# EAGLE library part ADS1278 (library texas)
Quad/Octal, Simultaneous Sampling, 24-Bit Analog-to-Digital Converters ADS1274 / ADS1278 Auto generated by make-symbol-device-package-bsdl.ulp Rev. 29 Source: http://focus.ti.com/lit/ds/symlink/ads1274.pdf
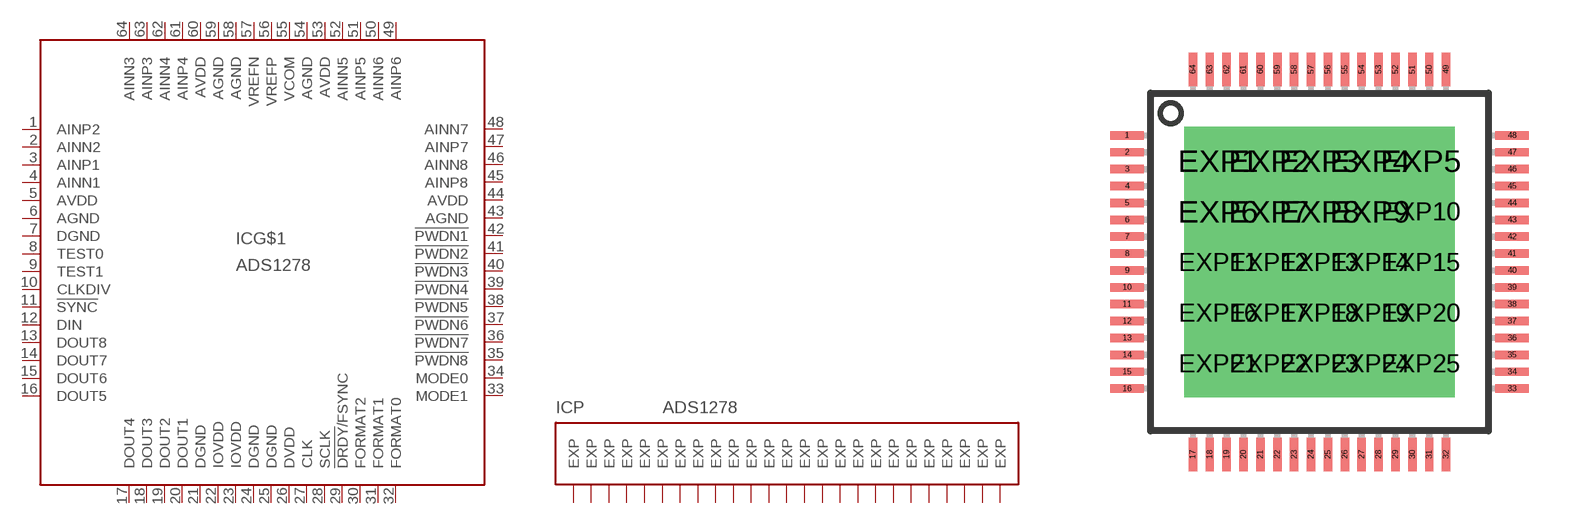
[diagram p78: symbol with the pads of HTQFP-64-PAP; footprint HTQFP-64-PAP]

Designator prefix IC; gates G$1=ADS1278 P=EXP25

## ADS1278 (MPN: ADS1278IPAPT; OC_FARNELL: 1603419; OC_NEWARK: 50M8811)  [HTQFP-64-PAP]
1  G$1:AINP2  in
2  G$1:AINN2  in
3  G$1:AINP1  in
4  G$1:AINN1  in
5  G$1:AVDD  pwr
6  G$1:AGND  pwr
7  G$1:DGND  pwr
8  G$1:TEST0  in
9  G$1:TEST1  in
10  G$1:CLKDIV  in
11  G$1:!SYNC  in
12  G$1:DIN  in
13  G$1:DOUT8  out
14  G$1:DOUT7  out
15  G$1:DOUT6  out
16  G$1:DOUT5  out
17  G$1:DOUT4  out
18  G$1:DOUT3  out
19  G$1:DOUT2  out
20  G$1:DOUT1  out
21  G$1:DGND  pwr
22  G$1:IOVDD  pwr
23  G$1:IOVDD  pwr
24  G$1:DGND  pwr
25  G$1:DGND  pwr
26  G$1:DVDD  pwr
27  G$1:CLK  in
28  G$1:SCLK
29  G$1:!DRDY!/FSYNC
30  G$1:FORMAT2  in
31  G$1:FORMAT1  in
32  G$1:FORMAT0  in
33  G$1:MODE1  in
34  G$1:MODE0  in
35  G$1:!PWDN8  in
36  G$1:!PWDN7  in
37  G$1:!PWDN6  in
38  G$1:!PWDN5  in
39  G$1:!PWDN4  in
40  G$1:!PWDN3  in
41  G$1:!PWDN2  in
42  G$1:!PWDN1  in
43  G$1:AGND  pwr
44  G$1:AVDD  pwr
45  G$1:AINP8  in
46  G$1:AINN8  in
47  G$1:AINP7  in
48  G$1:AINN7  in
49  G$1:AINP6  in
50  G$1:AINN6  in
51  G$1:AINP5  in
52  G$1:AINN5  in
53  G$1:AVDD  pwr
54  G$1:AGND  pwr
55  G$1:VCOM  out
56  G$1:VREFP  in
57  G$1:VREFN  in
58  G$1:AGND  pwr
59  G$1:AGND  pwr
60  G$1:AVDD  pwr
61  G$1:AINP4  in
62  G$1:AINN4  in
63  G$1:AINP3  in
64  G$1:AINN3  in
EXP1  P:EXP  pas
EXP2  P:EXP  pas
EXP3  P:EXP  pas
EXP4  P:EXP  pas
EXP5  P:EXP  pas
EXP6  P:EXP  pas
EXP7  P:EXP  pas
EXP8  P:EXP  pas
EXP9  P:EXP  pas
EXP10  P:EXP  pas
EXP11  P:EXP  pas
EXP12  P:EXP  pas
EXP13  P:EXP  pas
EXP14  P:EXP  pas
EXP15  P:EXP  pas
EXP16  P:EXP  pas
EXP17  P:EXP  pas
EXP18  P:EXP  pas
EXP19  P:EXP  pas
EXP20  P:EXP  pas
EXP21  P:EXP  pas
EXP22  P:EXP  pas
EXP23  P:EXP  pas
EXP24  P:EXP  pas
EXP25  P:EXP  pas

## Footprint HTQFP-64-PAP (pad centres in mm)
PAP (S-PQFP-G46) PowerPAD Package Source: http://focus.ti.com/lit/ds/symlink/ads1274.pdf www.ti.com .. slma002.pdf
smd 1 x 0.25: 1 -5.7,3.75; 2 -5.7,3.25; 3 -5.7,2.75; 4 -5.7,2.25; 5 -5.7,1.75; 6 -5.7,1.25; 7 -5.7,0.75; 8 -5.7,0.25; 9 -5.7,-0.25; 10 -5.7,-0.75; 11 -5.7,-1.25; 12 -5.7,-1.75; 13 -5.7,-2.25; 14 -5.7,-2.75; 15 -5.7,-3.25; 16 -5.7,-3.75; 33 5.7,-3.75; 34 5.7,-3.25; 35 5.7,-2.75; 36 5.7,-2.25; 37 5.7,-1.75; 38 5.7,-1.25; 39 5.7,-0.75; 40 5.7,-0.25; 41 5.7,0.25; 42 5.7,0.75; 43 5.7,1.25; 44 5.7,1.75; 45 5.7,2.25; 46 5.7,2.75; 47 5.7,3.25; 48 5.7,3.75
smd 0.25 x 1: 17 -3.75,-5.7; 18 -3.25,-5.7; 19 -2.75,-5.7; 20 -2.25,-5.7; 21 -1.75,-5.7; 22 -1.25,-5.7; 23 -0.75,-5.7; 24 -0.25,-5.7; 25 0.25,-5.7; 26 0.75,-5.7; 27 1.25,-5.7; 28 1.75,-5.7; 29 2.25,-5.7; 30 2.75,-5.7; 31 3.25,-5.7; 32 3.75,-5.7; 49 3.75,5.7; 50 3.25,5.7; 51 2.75,5.7; 52 2.25,5.7; 53 1.75,5.7; 54 1.25,5.7; 55 0.75,5.7; 56 0.25,5.7; 57 -0.25,5.7; 58 -0.75,5.7; 59 -1.25,5.7; 60 -1.75,5.7; 61 -2.25,5.7; 62 -2.75,5.7; 63 -3.25,5.7; 64 -3.75,5.7
drill 0.3 pad 2 square: EXP1 -3,3; EXP2 -1.5,3; EXP3 0,3; EXP4 1.5,3; EXP5 3,3; EXP6 -3,1.5; EXP7 -1.5,1.5; EXP8 0,1.5; EXP9 1.5,1.5; EXP10 3,1.5; EXP11 -3,0; EXP12 -1.5,0; EXP13 0,0; EXP14 1.5,0; EXP15 3,0; EXP16 -3,-1.5; EXP17 -1.5,-1.5; EXP18 0,-1.5; EXP19 1.5,-1.5; EXP20 3,-1.5; EXP21 -3,-3; EXP22 -1.5,-3; EXP23 0,-3; EXP24 1.5,-3; EXP25 3,-3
